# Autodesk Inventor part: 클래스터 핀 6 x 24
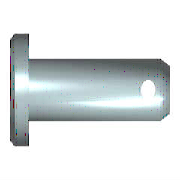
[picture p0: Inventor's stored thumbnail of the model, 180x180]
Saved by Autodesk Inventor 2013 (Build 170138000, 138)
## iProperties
IsCustomPart: 1
Created: 2012-02
Part Number: 클래스터 핀 6 x 24
Material: 강철
Description: 머리가 있는 클레비스 핀
Document SubType Name: Modeling
Standard: ISO 2341
Designer: mduedu
Standard Revision: Second edition 1986-11-01
Standards Organization: ISO
Language: ko-KR
Size Designation: B - 6 x 24
Categories: <MemberInstance><Categories><Category DisplayName="조임쇠" InternalName="e4da775c-781d-43d5-af7c-5136215cf5a6" Mnemonic="FSTN"><Category DisplayName="핀" InternalNa
Density: 7.85 g/cm^3
Author: mduedu
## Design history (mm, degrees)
sketch "스케치1"
  geometry: L1 (-2, 0)-(-2, 5); L2 (-2, 5)-(0, 5); L3 (0, 5)-(0, 3); L4 (0, 3)-(24, 3); L5 (24, 3)-(24, 0); L6 (-2, 0)-(24, 0); L7 (-4, 0)-(17, 0) reference; L8 (0, -0.98)-(0, 3.08) reference; C1 r 0.8 at (20.8, 0)
  constraints: 12 end point, 3 parallel, 2 collinear, 2 perpendicular, 1 centre point, 1 point on line, 1 vertical
  dimensions: "d0" = 6 diameter of L4 L6 (= NND); "d1" = 10 diameter of L2 L6 (= KOD); "d2" = 2 distance of L1.end L2.end (= KOH); "d3" = 24 distance of L3.end L4.end (= NLG); "d5" = 3.2 distance from line of L5 C1.centre (= DIST); "d6" = 1.6 diameter of C1 (= BOR)
revolve "본체" stored, may be unused: angle "d4" = 90 deg
extrude "구멍" cut sketch "스케치1" stored distance "d7" = 6 (= NND); taper "d8" = 0 deg
workaxis "Work Axis1"
workplane "Work Plane1"
node "작업축3"
body "Solid1"
chamfer "모따기1" distance "d9" = 1 (= PHH2); stored, may be unused: angle "d10" = 45 deg (= FAWI2), second distance "d16" = 1 (= PHH2)
chamfer "모따기2" distance "d11" = 2 (= PHH1); stored, may be unused: angle "d12" = 30 deg (= FAWI1), second distance "d17" = 2 (= PHH1)
other parameters: "PHH1" = 2 [user parameter; used in 2 equation terms], "PHH2" = 1 [user parameter; used in 2 equation terms], "KOD" = 10 [user parameter; used in 1 equation term], "KOH" = 2 [user parameter; used in 1 equation term], "NND" = 6 [user parameter; used in 2 equation terms], "FAWI1" = 30 deg [user parameter; used in 1 equation term], "FAWI2" = 45 deg [user parameter; used in 1 equation term], "DIST" = 3.2 [user parameter; used in 1 equation term], "BOR" = 1.6 [user parameter; used in 1 equation term], "NLG" = 24 [user parameter; used in 1 equation term], "d13" = 0, "d14" = 0, "d27" = 0, "d28" = 0, "d29" = 0, "d30" = 0, "d31" = 0
